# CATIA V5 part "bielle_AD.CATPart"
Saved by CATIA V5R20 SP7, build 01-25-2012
Part number: bielle_AD
Bounding box of the stored display mesh (mm): x -62.072 to 50.736, y 25 to 35, z -17.072 to 80.763
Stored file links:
  C:\Users\Matthieu\Desktop\IAO_2012_mcamard_Catia\bielle_AD.CATPart
  C:\Users\Matthieu\Desktop\IAO_Artobolevsky\Artobolevsky_786.CATProduct
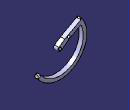
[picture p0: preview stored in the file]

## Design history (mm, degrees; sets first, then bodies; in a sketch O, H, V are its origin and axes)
Sketch1 on Plane1, origin (0, 0, 0), H (-1, 0, 0), V (0, 0, 1)
  construction line L1 (0, 45) -> (20.4337, 59.4036)
  point P1 (0, 45)
  point P2 (20.4337, 59.4036)
  line L2 (-2.8807, 49.0867) -> (10.9676, 58.8483)
  line L3 (23.3144, 55.3168) -> (2.8807, 40.9133)
  arc A1 centre (0, 45) radius 5 from (2.8807, 40.9133) to (-2.8807, 49.0867) cw
  circle A2 centre (0, 45) radius 3
  circle A3 centre (20.4337, 59.4036) radius 3
  reference projected point E1 (0, 45) from Point1
  reference projected point E2 (20.4337, 59.4036) from DatumPoint1
  line L4 (23.3144, 55.3168) -> (50, 70)
  line L5 (50, 80) -> (10.9676, 58.8483)
  line L6 (50, 80) -> (50, 70)
  distance L1 L2 = 5
  tangency: A1 L2, A1 L3
  coincidence: P1 E1, P2 E2
  vertical: L6 V
Sketch2 on Plane2, origin (21.1909, 0, 30.0627), H (0, 1, 0), V (-0.8173, 0, 0.5761)
  line L1 (25, 88) -> (35, 88)
  line L2 (35, 88) -> (35, 80)
  line L3 (35, 80) -> (25, 80)
  line L4 (25, 80) -> (25, 88)
  reference projected line E1 (0, -29.0736) -> (0, 80.9264) from edge of DatumCurve1
  length L1 = 10
  length L2 = 8
  distance L4 E1 = 25
  horizontal: L1 H, L3 H
  vertical: L2 V, L4 V
Sweep1: type Unspec, Profile Sketch2, Guide DatumCurve1
Fill1: Boundary (edge of Sweep1; edge of Sweep1; edge of Sweep1; edge of Sweep1)
Set1
  Plane1: linked copy from another document
  Point1 "A": linked copy from another document
  DatumPoint1: linked copy from another document
  Line1: linked copy from another document
  Line2: linked copy from another document
  DatumCurve1: linked copy from another document
Body1 (main body)
  Plane2: type 2Lines, Element1 Line1, Element2 Line2
  Fill2: Boundary Sketch2
  Pad1: profile Sketch1, direction (0, 1, 0), length 35, opposite side length -25
  ThickSurface1: Surface Sweep1, TopOffset 4, BotOffset 0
